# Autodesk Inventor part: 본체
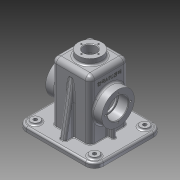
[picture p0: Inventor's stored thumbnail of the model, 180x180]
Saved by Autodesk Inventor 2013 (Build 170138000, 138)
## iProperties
Created: 2016-01
Part Number: 본체
Material: 알루미늄 6061
Document SubType Name: Modeling
Designer: User
Density: 2.71 g/cm^3
Mass: 989.778 g
Surface Area: 902.457 cm^2
Volume: 365.232 cm^3
Author: User
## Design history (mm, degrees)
sketch "스케치1"
  geometry: L1 (-65, 57.5)-(65, 57.5); L2 (65, 57.5)-(65, -57.5); L3 (65, -57.5)-(-65, -57.5); L4 (-65, -57.5)-(-65, 57.5); 3 further points
  constraints: 8 end point, 2 midpoint, 2 parallel, 1 horizontal, 1 horizontal alignment, 1 perpendicular, 1 vertical alignment
  dimensions: "d0" = 130 distance of L1.start L1.end; "d2" = 115 distance of L3.end L1.start
extrude "돌출1" new body sketch "스케치1" distance "d3" = 8; taper "d4" = 0 deg
sketch "스케치2"
  geometry: L1 (-32.5, 32.5)-(32.5, 32.5); L2 (32.5, 32.5)-(32.5, -32.5); L3 (32.5, -32.5)-(-32.5, -32.5); L4 (-32.5, -32.5)-(-32.5, 32.5); 3 further points
  constraints: 8 end point, 2 midpoint, 2 parallel, 1 horizontal, 1 horizontal alignment, 1 perpendicular, 1 vertical alignment
  dimensions: "d5" = 65 distance of L1.start L1.end; "d7" = 65 distance of L1.end L2.end
extrude "돌출2" join sketch "스케치2" distance "d8" = 100; taper "d9" = 0 deg
sketch "스케치3"
  geometry: C1 r 20 at (0, 0); 1 further point
  constraints: 1 centre point, 1 coincident
  dimensions: "d10" = 40 diameter of C1
extrude "돌출3" join sketch "스케치3" distance "d11" = 10; taper "d12" = 0 deg
sketch "스케치4"
  geometry: L1 (-32.5, 8)-(-32.5, 108) reference; L2 (-32.5, 8)-(32.5, 8) reference; L3 (-32.5, 8)-(-32.5, 108) reference; L4 (32.5, 108)-(-32.5, 108) reference; L5 (32.5, 8)-(32.5, 108) reference; L6 (57.5, 8)-(-57.5, 8) reference; C1 r 27.5 at (0, 55); 1 further point
  constraints: 1 centre point, 1 vertical alignment
  dimensions: "d13" = 55 diameter of C1; "d14" = 55 distance of C1.centre point (0, 0)
  node "투영된 루프1"
fillet "모깎기1" dims "d15" = 8
extrude "돌출4" join sketch "스케치4" stored distance "d16" = 95; taper "d17" = 0 deg
fillet "모깎기2" dims "d18" = 8
hole "구멍1" diameter "d21" = 21; stored, may be unused: countersink angle "d25" = 90 deg, drill point angle "d27" = 118 deg; dims "d19" = 10, "d20" = 10, "d22" = 6, "d23" = 4, "d24" = 2, "d26" = 8
sketch "스케치5"
  geometry: L1 (-57.5, 0)-(57.5, 0) reference; L2 (-57.5, 0)-(-57.5, 8) reference; L3 (57.5, 8)-(-57.5, 8) reference; L4 (57.5, 0)-(57.5, 8) reference; L5 (-57.5, 2)-(-57.5, 2); L6 (-57.5, 2)-(-57.5, 0); L7 (57.5, 2)-(57.5, 2); L8 (57.5, 2)-(57.5, 0); 7 further points; 4 other entities
  constraints: 8 end point, 4 point on line, 2 horizontal, 2 perpendicular, 4 other
  dimensions: "d28" = 25 dimension on L6; "d29" = 2 distance between parallel lines of L1 L5; "d30" = 2 distance between parallel lines of L1 L7; "d31" = 25 dimension on L8
extrude "돌출5" cut sketch "스케치5" stored distance "d32" = 140; taper "d33" = 0 deg
sketch "스케치6"
  geometry: L1 (32.5, 24.5)-(32.5, -24.5) reference; L2 (65, -57.5)-(65, 57.5) reference; L3 (32.5, 3)-(42.5, 3); L4 (42.5, 3)-(42.5, -3); L5 (42.5, -3)-(32.5, -3); L6 (-27.5, 27.5)-(27.5, 27.5); L7 (27.5, 27.5)-(27.5, -27.5); L8 (27.5, -27.5)-(-27.5, -27.5); L9 (-27.5, -27.5)-(-27.5, 27.5); 4 further points
  constraints: 14 end point, 3 midpoint, 3 parallel, 3 perpendicular, 2 horizontal alignment, 2 point on line, 1 horizontal, 1 vertical alignment
  dimensions: "d34" = 6 distance between parallel lines of L5 L3; "d169" = 55 distance of L6.start L6.end; "d170" = 55 distance of L8.end L6.start; "d171" = 15 distance of point (42.5, 0) point (27.5, 0)
sketch "스케치8"
  geometry: L1 (-27.5, 27.5)-(27.5, 27.5); L2 (27.5, 27.5)-(27.5, -27.5); L3 (27.5, -27.5)-(-27.5, -27.5); L4 (-27.5, -27.5)-(-27.5, 27.5); C1 r 10.5 at (0, 0) reference; 2 further points
  constraints: 8 end point, 2 midpoint, 2 parallel, 1 horizontal, 1 horizontal alignment, 1 perpendicular, 1 vertical alignment
  dimensions: "d38" = 55 distance of L1.start L1.end; "d40" = 55 distance of L1.end L2.end
extrude "돌출7" cut sketch "스케치8" distance "d41" = 105; taper "d42" = 0 deg
hole "구멍2" diameter "d45" = 35; stored, may be unused: countersink angle "d49" = 90 deg, drill point angle "d51" = 0 deg; dims "d43" = 10, "d44" = 10, "d46" = 6, "d47" = 35, "d48" = 17, "d50" = 17
hole "구멍3" diameter "d54" = 35; stored, may be unused: countersink angle "d58" = 90 deg, drill point angle "d60" = 0 deg; dims "d52" = 10, "d53" = 10, "d55" = 6, "d56" = 35, "d57" = 17, "d59" = 17
hole "구멍4" diameter "d63" = 30; stored, may be unused: countersink angle "d67" = 90 deg, drill point angle "d69" = 0 deg; dims "d61" = 10, "d62" = 10, "d64" = 6, "d65" = 35, "d66" = 17, "d68" = 28.5
hole "구멍5" diameter "d72" = 30; stored, may be unused: countersink angle "d76" = 90 deg, drill point angle "d78" = 0 deg; dims "d70" = 10, "d71" = 10, "d73" = 6, "d74" = 35, "d75" = 17, "d77" = 28.5
sketch "스케치9"
  geometry: L1 (47.5, 8)-(32.5, 93.069); L2 (32.5, 100)-(32.5, 8) reference; L3 (57.5, 8)-(-57.5, 8) reference; L4 (57.5, 0)-(57.5, 8) reference; 1 further point
  constraints: 2 end point, 2 point on line
  dimensions: "d79" = 10 distance of L3.start L1.start; "d80" = 10 deg angle of L1 L4
feature "리브1" sketch "스케치9" dims "d81" = 1, "d82" = 10, "d83" = 0, "d84" = 0, "d85" = 1, "d86" = 1
fillet "모깎기3" dims "d87" = 15
sketch "스케치10"
  geometry: L1 (-65, -42.5)-(-65, 42.5) reference; L2 (-50, 57.5)-(50, 57.5) reference; L3 (65, 42.5)-(65, -42.5) reference; L4 (50, -57.5)-(-50, -57.5) reference; L5 (27.5, 27.5)-(-27.5, 27.5) reference; L6 (-27.5, 27.5)-(-27.5, -27.5) reference; L7 (-27.5, -27.5)-(27.5, -27.5) reference; L8 (27.5, -27.5)-(27.5, 27.5) reference; L9 (24.5, -32.5)-(5, -32.5) reference; L10 (5, -32.5)-(5, -47.5) reference; L11 (5, -47.5)-(-5, -47.5) reference; L12 (-5, -47.5)-(-5, -32.5) reference; L13 (-5, -32.5)-(-24.5, -32.5) reference; L14 (-32.5, -24.5)-(-32.5, 24.5) reference; L15 (-24.5, 32.5)-(-5, 32.5) reference; L16 (-5, 32.5)-(-5, 47.5) reference; L17 (-5, 47.5)-(5, 47.5) reference; L18 (5, 47.5)-(5, 32.5) reference; L19 (5, 32.5)-(24.5, 32.5) reference; L20 (32.5, 24.5)-(32.5, -24.5) reference; C1 r 7.5 at (-50, 42.5); C2 r 7.5 at (50, 42.5); C3 r 7.5 at (50, -42.5); C4 r 7.5 at (-50, -42.5); A1 r 15 centre (-50, -42.5) between (-65, -42.5) and (-50, -57.5) reference; A2 r 15 centre (-50, 42.5) between (-50, 57.5) and (-65, 42.5) reference; A3 r 15 centre (50, 42.5) between (65, 42.5) and (50, 57.5) reference; A4 r 15 centre (50, -42.5) between (50, -57.5) and (65, -42.5) reference; A5 r 8 centre (24.5, -24.5) between (24.5, -32.5) and (32.5, -24.5) reference; A6 r 8 centre (-24.5, -24.5) between (-32.5, -24.5) and (-24.5, -32.5) reference; A7 r 8 centre (-24.5, 24.5) between (-24.5, 32.5) and (-32.5, 24.5) reference; A8 r 8 centre (24.5, 24.5) between (32.5, 24.5) and (24.5, 32.5) reference; 1 further point
  constraints: 4 centre point, 4 coincident
  dimensions: "d88" = 15 diameter of C1; "d89" = 15 diameter of C2; "d90" = 15 diameter of C3; "d91" = 15 diameter of C4
extrude "돌출8" join sketch "스케치10" distance "d92" = 3; taper "d93" = 0 deg
hole "구멍6" diameter "d96" = 6; stored, may be unused: countersink angle "d100" = 90 deg, drill point angle "d102" = 0 deg; dims "d94" = 10, "d95" = 10, "d97" = 6, "d98" = 35, "d99" = 17, "d101" = 28.5
hole "구멍7" diameter "d105" = 6; stored, may be unused: countersink angle "d109" = 90 deg, drill point angle "d111" = 0 deg; dims "d103" = 10, "d104" = 10, "d106" = 6, "d107" = 35, "d108" = 17, "d110" = 28.5
hole "구멍8" diameter "d114" = 6; stored, may be unused: countersink angle "d118" = 90 deg, drill point angle "d120" = 0 deg; dims "d112" = 10, "d113" = 10, "d115" = 6, "d116" = 35, "d117" = 17, "d119" = 28.5
hole "구멍9" diameter "d123" = 6; stored, may be unused: countersink angle "d127" = 90 deg, drill point angle "d129" = 0 deg; dims "d121" = 10, "d122" = 10, "d124" = 6, "d125" = 35, "d126" = 17, "d128" = 28.5
sketch "스케치11" dims "d130" = 42
  geometry: A1 r 27.5 centre (-55, 0) between (-55, 27.5) and (-55, 27.5) reference; 3 further points
  constraints: 1 coincident, 1 horizontal alignment, 2 other
hole "구멍10" sketch "스케치11" at (-76, 0) diameter "d131" = 3.242; stored, may be unused: countersink angle "d135" = 90 deg, drill point angle "d137" = 118 deg; dims "d132" = 8, "d133" = 35, "d134" = 17, "d136" = 10
sketch "스케치12" dims "d141" = 29
  geometry: C1 r 10.5 at (0, 0) reference; 2 further points
  constraints: 2 vertical alignment, 1 coincident, 2 other
hole "구멍11" sketch "스케치12" at (0, 14.5) diameter "d142" = 2.459; stored, may be unused: countersink angle "d146" = 90 deg, drill point angle "d148" = 118 deg; dims "d143" = 7, "d144" = 35, "d145" = 17, "d147" = 9
fillet "모깎기4" dims "d152" = 0.3
chamfer "모따기1" distance "d153" = 1; stored, may be unused: second distance "d154" = 2, angle "d155" = 45 deg
chamfer "모따기2" distance "d156" = 1; stored, may be unused: second distance "d157" = 2, angle "d158" = 45 deg
sketch "스케치13" dims "d177" = 3
  geometry: L1 (-27.5, 27.5)-(27.5, 27.5) reference; L2 (27.5, 27.5)-(27.5, -27.5) reference; L3 (27.5, -27.5)-(-27.5, -27.5) reference; L4 (-27.5, -27.5)-(-27.5, 27.5) reference; L5 (-60, 52.5)-(60, 52.5); L6 (60, 52.5)-(60, -52.5); L7 (60, -52.5)-(-60, -52.5); L8 (-60, -52.5)-(-60, 52.5); C1 r 3 at (50, 42.5) reference; C2 r 3 at (50, -42.5) reference; C3 r 3 at (-50, -42.5) reference; C4 r 3 at (-50, 42.5) reference; 3 further points
  constraints: 8 end point, 2 midpoint, 2 parallel, 1 horizontal, 1 horizontal alignment, 1 perpendicular, 1 vertical alignment
  dimensions: "d159" = 120 distance of L5.start L5.end; "d162" = 105 distance between parallel lines of L5 L7
extrude "돌출9" join sketch "스케치13" distance "d163" = 2; taper "d164" = 0 deg
fillet "모깎기5" dims "d165" = 10
fillet "모깎기6" dims "d166" = 3
fillet "모깎기7" dims "d167" = 3
fillet "모깎기8" dims "d168" = 3
fillet "모깎기13" dims "d176" = 3
fillet "모깎기14" dims "d177" = 3
chamfer "모따기3" distance "d179" = 1; stored, may be unused: second distance "d180" = 2, angle "d181" = 45 deg
fillet "모깎기16" dims "d182" = 3
sketch "스케치14"
  geometry: L1 (0, -8)-(92, -8) reference; L2 (-18, 44.5)-(-18, 4.5) reference; 3 further points
  constraints: 1 other
  dimensions: "d183" = 32.5 distance from line of point (8, 24.5) L1; "d184" = 26 distance from line of point (8, 24.5) L2
feature "엠보싱1" sketch "스케치14" dims "d185" = 0.5, "d186" = 0
fillet "모깎기17" dims "d187" = 3
node "작업 평면1"
extrude "돌출11" join sketch "스케치6" stored distance "d190" = 10; taper "d191" = 0 deg
fillet "모깎기18" dims "d192" = 3
fillet "모깎기19" dims "d193" = 3
fillet "모깎기20" dims "d194" = 3
fillet "모깎기21" dims "d195" = 3
fillet "모깎기22" dims "d196" = 1
node "솔리드1"
mirror "대칭2"
pattern_circular "원형 패턴1" dims angle "d139" = 360 deg
mirror "대칭3"
pattern_circular "원형 패턴2" dims angle "d150" = 360 deg
mirror "대칭4"
node "투영된 루프2"
node "절단 모서리 투영1"
